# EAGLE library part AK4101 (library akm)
Digital Audio Transmitter (DIT) Quad Output, 24-Bit, 192 kHz
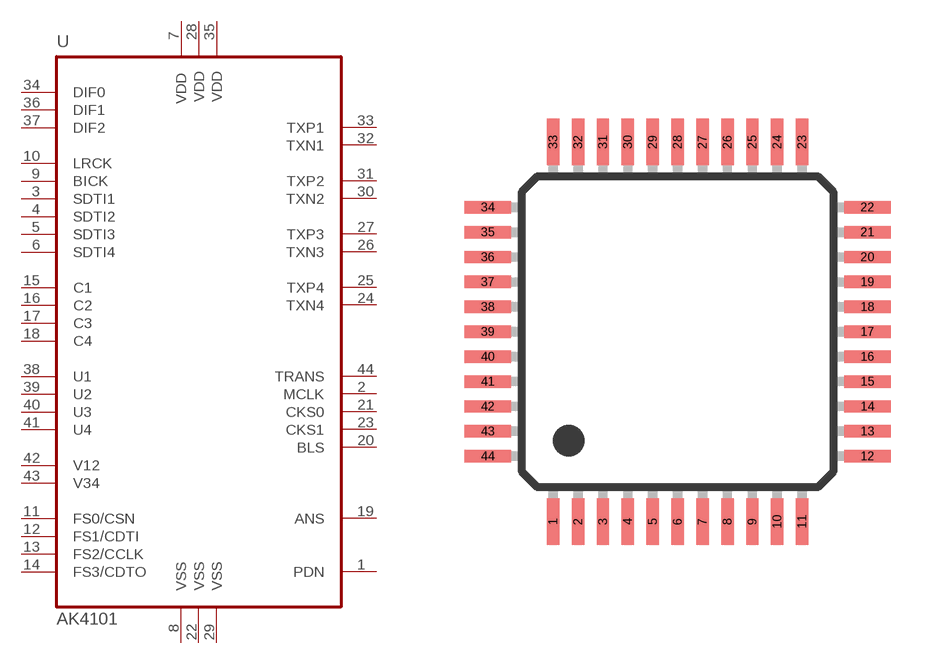
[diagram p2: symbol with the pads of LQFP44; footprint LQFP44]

Designator prefix U

## AK4101AV  [LQFP44]
1  PDN
2  MCLK
3  SDTI1
4  SDTI2
5  SDTI3
6  SDTI4
7  VDD
8  VSS
9  BICK
10  LRCK
11  FS0/CSN
12  FS1/CDTI
13  FS2/CCLK
14  FS3/CDTO
15  C1
16  C2
17  C3
18  C4
19  ANS
20  BLS
21  CKS0
22  VSS1
23  CKS1
24  TXN4
25  TXP4
26  TXN3
27  TXP3
28  VDD1
29  VSS2
30  TXN2
31  TXP2
32  TXN1
33  TXP1
34  DIF0
35  VDD2
36  DIF1
37  DIF2
38  U1
39  U2
40  U3
41  U4
42  V12
43  V34
44  TRANS

## Footprint LQFP44 (pad centres in mm)
LQFP44
smd 0.4 x 1.5: 1 -4,-6.1; 2 -3.2,-6.1; 3 -2.4,-6.1; 4 -1.6,-6.1; 5 -0.8,-6.1; 6 0,-6.1; 7 0.8,-6.1; 8 1.6,-6.1; 9 2.4,-6.1; 10 3.2,-6.1; 11 4,-6.1; 23 4,6.1; 24 3.2,6.1; 25 2.4,6.1; 26 1.6,6.1; 27 0.8,6.1; 28 0,6.1; 29 -0.8,6.1; 30 -1.6,6.1; 31 -2.4,6.1; 32 -3.2,6.1; 33 -4,6.1
smd 1.5 x 0.4: 12 6.1,-4; 13 6.1,-3.2; 14 6.1,-2.4; 15 6.1,-1.6; 16 6.1,-0.8; 17 6.1,0; 18 6.1,0.8; 19 6.1,1.6; 20 6.1,2.4; 21 6.1,3.2; 22 6.1,4; 34 -6.1,4; 35 -6.1,3.2; 36 -6.1,2.4; 37 -6.1,1.6; 38 -6.1,0.8; 39 -6.1,0; 40 -6.1,-0.8; 41 -6.1,-1.6; 42 -6.1,-2.4; 43 -6.1,-3.2; 44 -6.1,-4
